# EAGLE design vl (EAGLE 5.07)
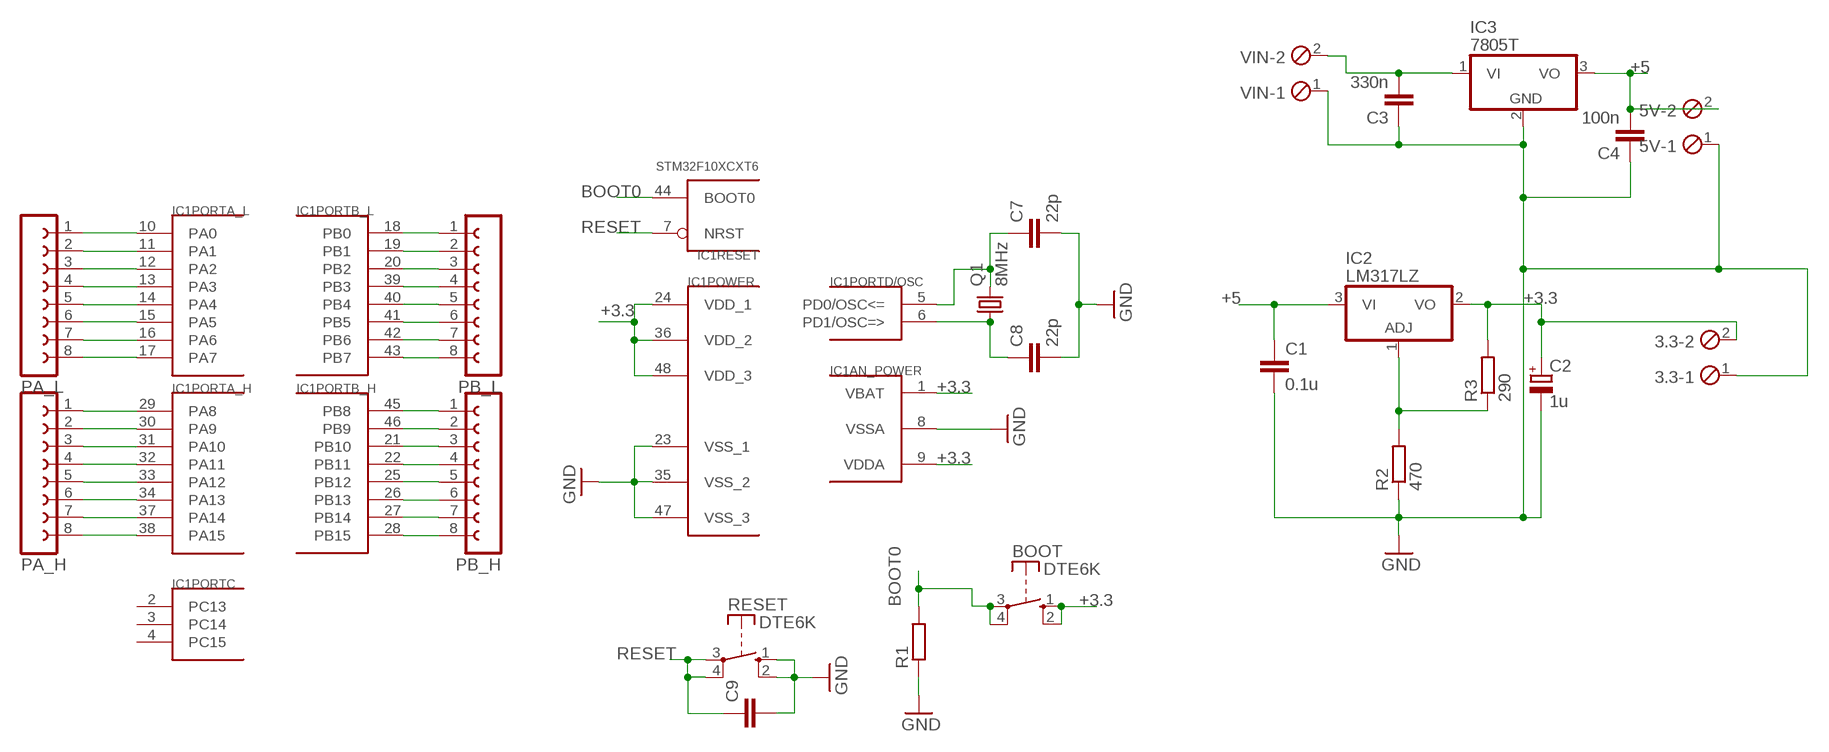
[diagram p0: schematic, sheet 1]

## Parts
3.3  MPT2  [2POL254]
5V  MPT2  [2POL254]
BOOT  DTE6K  [DTE6K]
C1  0.1u  C-EUC0805  [C0805]
C2  1u  CPOL-EUE2.5-6  [E2,5-6]
C3  330n  C-EUC0805  [C0805]
C4  100n  C-EUC0805  [C0805]
C7  22p  C-EUC0805  [C0805]
C8  22p  C-EUC0805  [C0805]
C9  C-EUC0805  [C0805]
IC1  STM32F10XCXT6  [TQFP48]
IC2  LM317LZ  [TO92]
IC3  7805T  [TO220H]
PA_H  FE08-1  [FE08]
PA_L  FE08-1  [FE08]
PB_H  FE08-1  [FE08]
PB_L  FE08-1  [FE08]
Q1  8MHz  CRYSTALHC49S  [HC49/S]
R1  R-EU_R0805  [R0805]
R2  470  R-EU_R0805  [R0805]
R3  290  R-EU_R0805  [R0805]
RESET  DTE6K  [DTE6K]
VIN  MPT2  [2POL254]

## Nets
+3.3: 3.3.2 BOOT.1(S) BOOT.2(S) C2.+ IC1.1(AN_POWER:VBAT) IC1.9(AN_POWER:VDDA) IC1.24(POWER:VDD_1) IC1.36(POWER:VDD_2) IC1.48(POWER:VDD_3) IC2.2(VO) R3.2
+5: 5V.2 C1.1 C4.2 IC2.3(VI) IC3.3(VO)
BOOT0: BOOT.3(P) BOOT.4(P) IC1.44(RESET:BOOT0) R1.2
GND: 3.3.1 5V.1 C1.2 C2.- C3.1 C4.1 C7.2 C8.2 C9.2 IC1.8(AN_POWER:VSSA) IC1.23(POWER:VSS_1) IC1.35(POWER:VSS_2) IC1.47(POWER:VSS_3) IC3.2(GND) R1.1 R2.1 RESET.1(S) RESET.2(S) VIN.1
N$1: C8.1 IC1.6(PORTD/OSC:PD1/OSC=>) Q1.1
N$2: C7.1 IC1.5(PORTD/OSC:PD0/OSC<=) Q1.2
N$3: IC1.10(PORTA_L:PA0) PA_L.1
N$4: IC1.11(PORTA_L:PA1) PA_L.2
N$5: IC2.1(ADJ) R2.2 R3.1
N$6: IC1.12(PORTA_L:PA2) PA_L.3
N$7: IC1.13(PORTA_L:PA3) PA_L.4
N$8: IC1.14(PORTA_L:PA4) PA_L.5
N$9: IC1.15(PORTA_L:PA5) PA_L.6
N$10: IC1.16(PORTA_L:PA6) PA_L.7
N$11: IC1.17(PORTA_L:PA7) PA_L.8
N$12: IC1.29(PORTA_H:PA8) PA_H.1
N$13: IC1.30(PORTA_H:PA9) PA_H.2
N$14: IC1.31(PORTA_H:PA10) PA_H.3
N$15: IC1.32(PORTA_H:PA11) PA_H.4
N$16: IC1.33(PORTA_H:PA12) PA_H.5
N$17: IC1.34(PORTA_H:PA13) PA_H.6
N$18: IC1.37(PORTA_H:PA14) PA_H.7
N$19: IC1.38(PORTA_H:PA15) PA_H.8
N$20: IC1.18(PORTB_L:PB0) PB_L.1
N$21: IC1.19(PORTB_L:PB1) PB_L.2
N$22: IC1.20(PORTB_L:PB2) PB_L.3
N$23: IC1.39(PORTB_L:PB3) PB_L.4
N$24: IC1.40(PORTB_L:PB4) PB_L.5
N$25: IC1.41(PORTB_L:PB5) PB_L.6
N$26: IC1.42(PORTB_L:PB6) PB_L.7
N$27: IC1.43(PORTB_L:PB7) PB_L.8
N$28: IC1.46(PORTB_H:PB9) PB_H.2
N$29: IC1.45(PORTB_H:PB8) PB_H.1
N$30: IC1.21(PORTB_H:PB10) PB_H.3
N$31: IC1.22(PORTB_H:PB11) PB_H.4
N$32: IC1.25(PORTB_H:PB12) PB_H.5
N$33: IC1.26(PORTB_H:PB13) PB_H.6
N$34: IC1.27(PORTB_H:PB14) PB_H.7
N$35: IC1.28(PORTB_H:PB15) PB_H.8
N$36: C3.2 IC3.1(VI) VIN.2
RESET: C9.1 IC1.7(RESET:NRST) RESET.3(P) RESET.4(P)
Unconnected: IC1.2(PORTC:PC13) IC1.3(PORTC:PC14) IC1.4(PORTC:PC15)

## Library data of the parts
3.3 5V VIN = con-phoenix-254:MPT2: PHOENIX CONNECTOR
BOOT RESET = switch-misc:DT: ITT SWITCH
C1 C3 C4 C7-C9 = resistor:C-EU: CAPACITOR, European symbol
C2 = resistor:CPOL-EU: POLARIZED CAPACITOR, European symbol
IC1 = stm32:STM32F10XCXT6: ST STM32F101/103 48pin LQFP
IC2 = linear:*317: Positive VOLTAGE REGULATOR
IC3 = linear:78*: Positive VOLTAGE REGULATOR Source: http://cache.national.com/ds/LM/LM78L05.pdf http://www.fairchildsemi.com/ds/LM/LM7805.pdf
PA_H PA_L PB_H PB_L = con-lsta:FE08-1: FEMALE HEADER
Q1 = crystal:CRYSTAL: CRYSTAL
R1-R3 = resistor:R-EU_: RESISTOR, European symbol

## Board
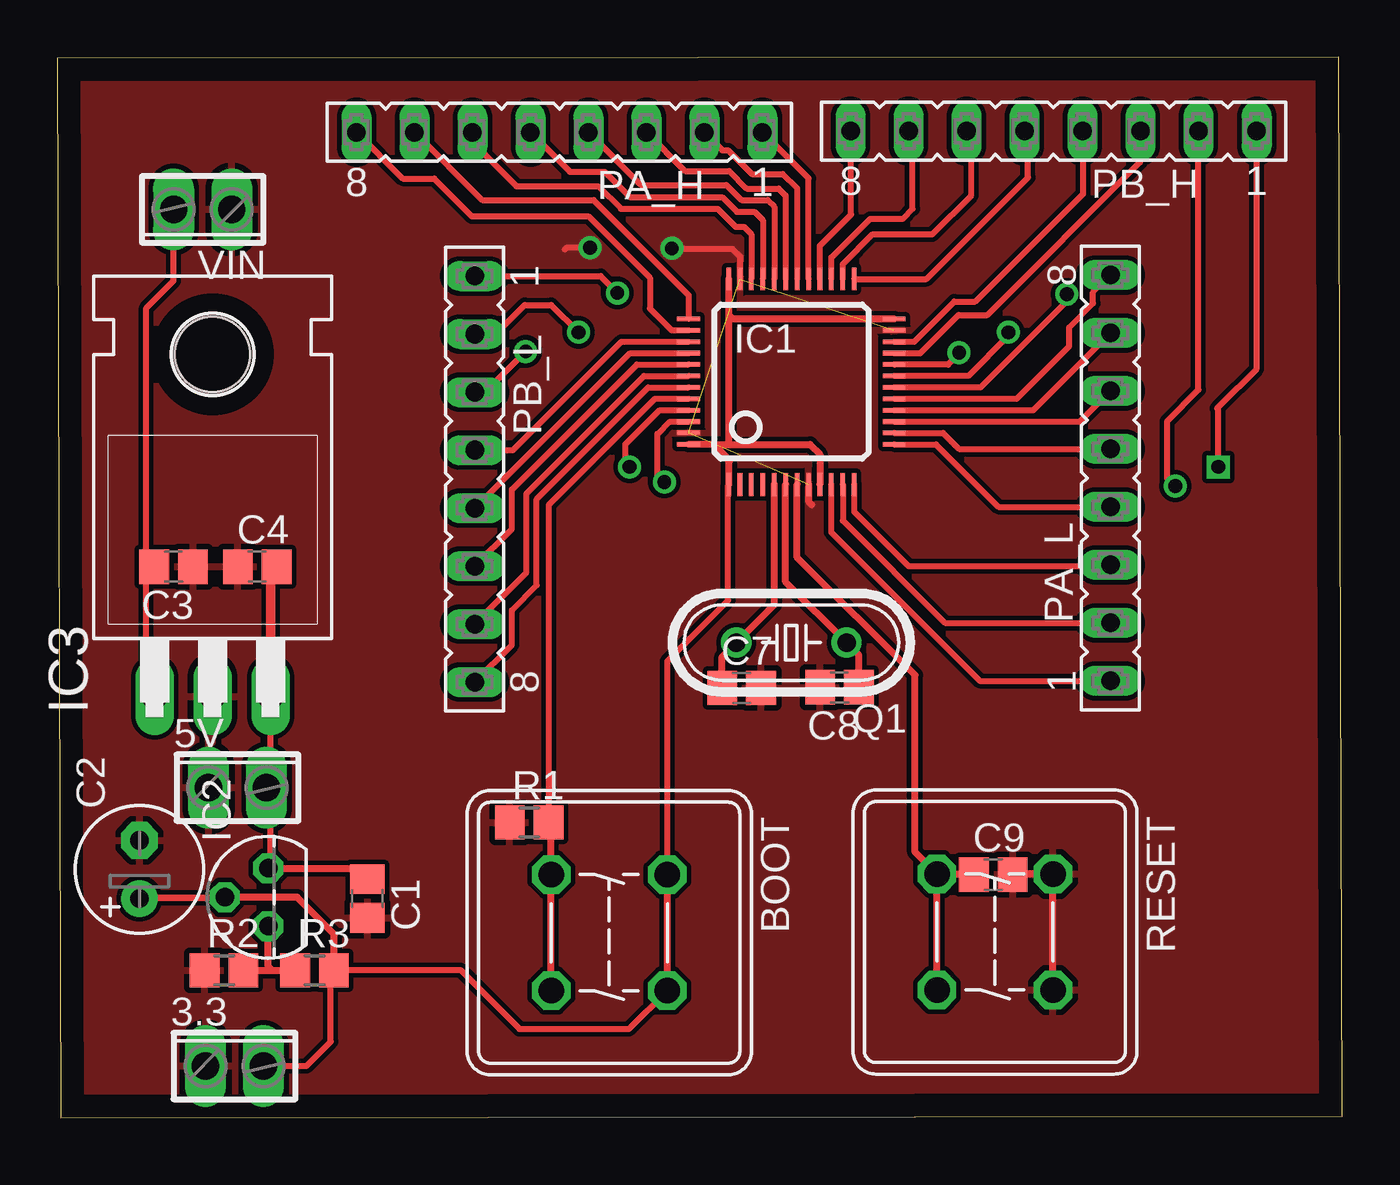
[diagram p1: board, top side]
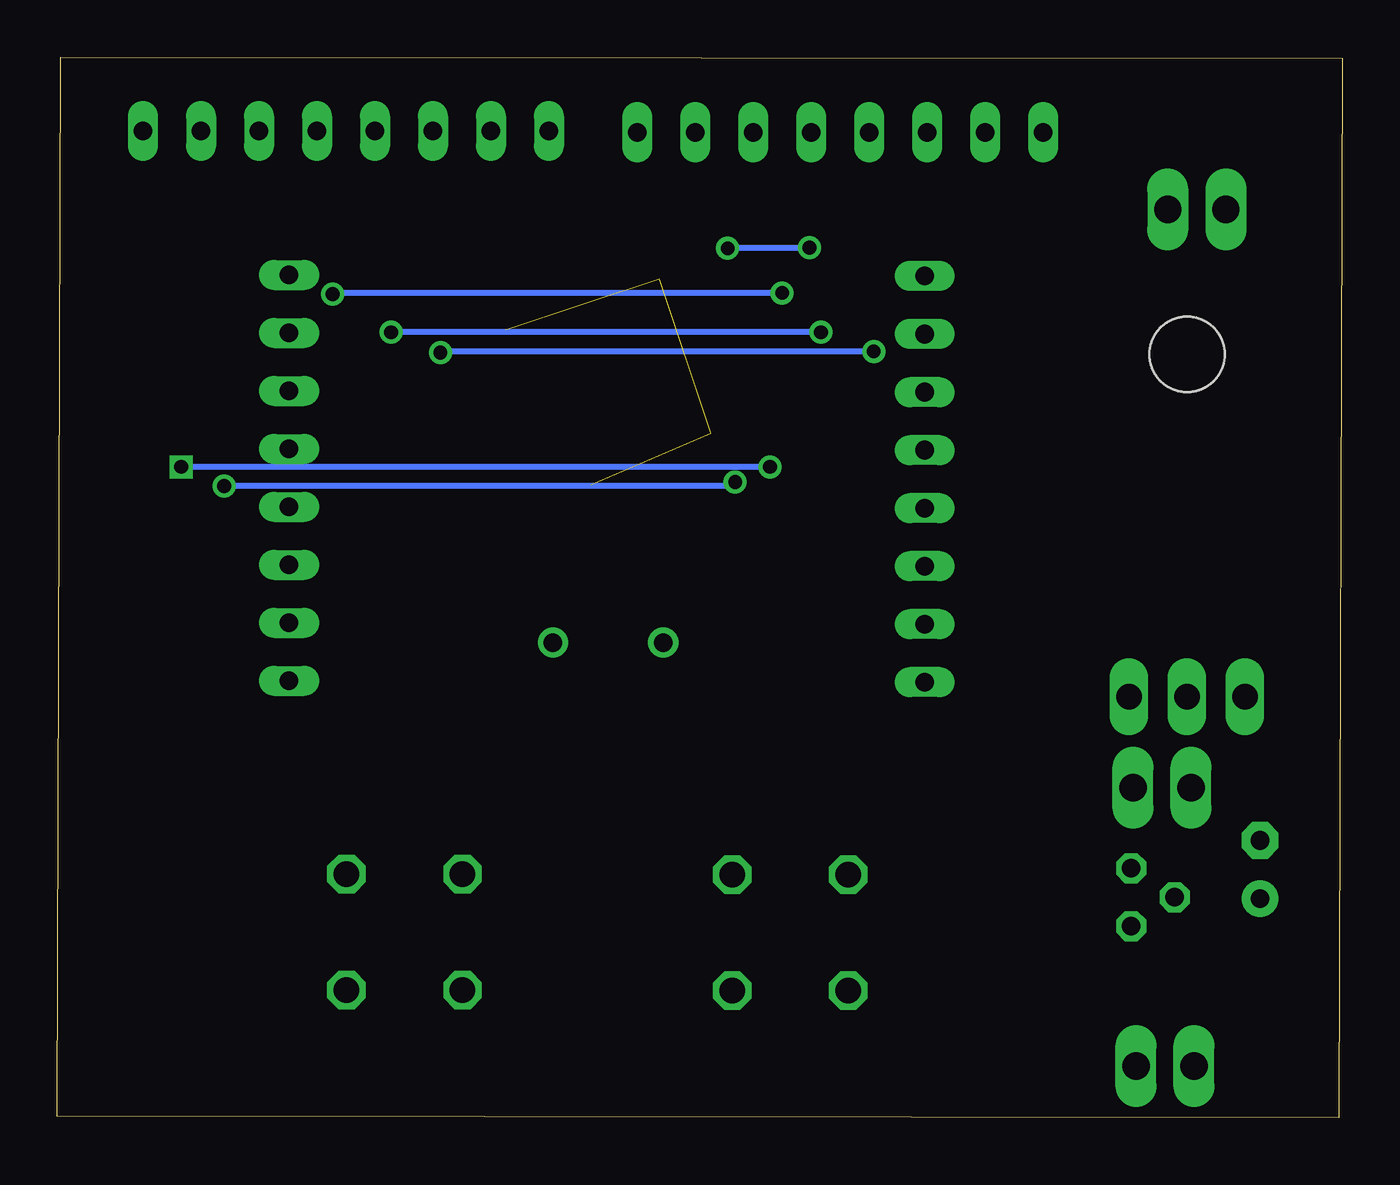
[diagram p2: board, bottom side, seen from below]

Size 56.29 x 46.45 mm. Coordinates in mm from the lower left corner, seen from the top.
Outline: 0.15,0 56.29,0.05 56.13,46.45 0,46.4 0.15,0
Copper layers (1*16): Top 0.035mm / dielectric 1.5mm / Bottom 0.035mm
Design rules "default": minimum track width 10mil, minimum drill 24mil, track to track 8mil, track to pad 8mil, pad to pad 8mil, via to via 8mil, smd to smd 8mil, copper to edge 40mil, drill to drill 8mil, minimum pad ring 10mil, minimum via ring 8mil, stop-mask expansion 4mil, vias tented up to drill 0mil, thermal gap 10mil

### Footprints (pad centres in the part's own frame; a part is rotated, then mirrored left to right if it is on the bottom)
2POL254 = drill 1.2 long: 1 -1.27,0; 2 1.27,0
DTE6K = drill 1.118 octagon: 1 -2.54,2.54; 2 2.54,2.54; 3 2.54,-2.54; 4 -2.54,-2.54
C0805 = smd 1.3 x 1.5: 1 -0.85,0; 2 0.85,0
E2,5-6 = drill 0.813 pad 1.6 round: + -1.27,0 | drill 0.813 pad 1.6 octagon: - 1.27,0
TQFP48 = smd 0.2 x 1: 1 -2.75,-4.5; 2 -2.25,-4.5; 3 -1.75,-4.5; 4 -1.25,-4.5; 5 -0.75,-4.5; 6 -0.25,-4.5; 7 0.25,-4.5; 8 0.75,-4.5; 9 1.25,-4.5; 10 1.75,-4.5; 11 2.25,-4.5; 12 2.75,-4.5; 25 2.75,4.5; 26 2.25,4.5; 27 1.75,4.5; 28 1.25,4.5; 29 0.75,4.5; 30 0.25,4.5; 31 -0.25,4.5; 32 -0.75,4.5; 33 -1.25,4.5; 34 -1.75,4.5; 35 -2.25,4.5; 36 -2.75,4.5 | smd 1 x 0.2: 13 4.5,-2.75; 14 4.5,-2.25; 15 4.5,-1.75; 16 4.5,-1.25; 17 4.5,-0.75; 18 4.5,-0.25; 19 4.5,0.25; 20 4.5,0.75; 21 4.5,1.25; 22 4.5,1.75; 23 4.5,2.25; 24 4.5,2.75; 37 -4.5,2.75; 38 -4.5,2.25; 39 -4.5,1.75; 40 -4.5,1.25; 41 -4.5,0.75; 42 -4.5,0.25; 43 -4.5,-0.25; 44 -4.5,-0.75; 45 -4.5,-1.25; 46 -4.5,-1.75; 47 -4.5,-2.25; 48 -4.5,-2.75
TO92 = drill 0.813 octagon: 1 -1.27,0; 2 0,1.905; 3 1.27,0
TO220H = drill 1.118 long: 1 -2.54,-10.16; 2 0,-10.16; 3 2.54,-10.16 | hole 3.302: 0,4.826
FE08 = drill 0.813 long: 1 -8.89,0; 2 -6.35,0; 3 -3.81,0; 4 -1.27,0; 5 1.27,0; 6 3.81,0; 7 6.35,0; 8 8.89,0
HC49/S = drill 0.813 round: 1 -2.413,0; 2 2.413,0
R0805 = smd 1.3 x 1.5: 1 -0.85,0; 2 0.85,0

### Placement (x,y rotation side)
3.3  7.77,2.26 0 top
5V  7.9,14.45 0 top
BOOT  24.18,8.1 270 top
C1  13.59,9.6 270 top
C2  3.61,10.87 90 top
C3  5.11,24.13 180 top
C4  8.76,24.13 0 top
C7  29.97,18.82 0 top
C8  34.26,18.85 180 top
C9  41,10.64 0 top
IC1  32.16,32.23 0 top
IC2  9.25,9.65 90 top
IC3  6.81,28.6 0 top
PA_H  22,43.15 180 top
PA_L  46.13,28.02 90 top
PB_H  43.64,43.21 180 top
PB_L  18.29,27.97 270 top
Q1  32.16,20.8 180 top
R1  20.68,12.93 0 top
R2  7.32,6.45 0 top
R3  11.28,6.45 0 top
RESET  41.07,8.13 270 top
VIN  6.38,39.78 180 top

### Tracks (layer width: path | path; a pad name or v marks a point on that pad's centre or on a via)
+3.3
  Top 0.254: 12.14,6.47 17.66,6.47 20.24,3.89 25.04,3.89 BOOT.2 | BOOT.1 26.72,19.99 29.39,22.66 29.39,27.71 IC1.1 | C2.+ 3.56,9.55 | 3.3.2 10.92,2.26 11.99,3.33 11.99,6.31 R3.2
  Top 0.305: 28.76,29.48 IC1.48 | 28.76,29.48 29.39,28.85 29.39,28.83 29.44,28.78 29.44,28.73 29.41,28.7 IC1.1 | 29.36,29.48 32.98,29.48 33.4,29.06 IC1.9 | 28.76,29.48 29.36,29.48 | 29.36,29.48 29.41,29.54 29.41,35.15 | 29.41,35.15 IC1.36 | 7.85,9.65 10.52,9.65 12.14,8.03 12.14,6.47 R3.2 | 7.85,9.65 IC2.2 | C2.+ 7.82,9.63 7.85,9.65 | IC1.24 29.58,34.98 29.41,35.15 | BOOT.2 BOOT.1
+5
  Top 0.254: 9.35,14.94 9.35,11.02 IC2.3 | 9.35,14.94 IC3.3 | 5V.2 9.17,14.76 9.35,14.94
  Top 0.305: IC2.3 13.12,10.92 C1.1
  Top 0.406: C4.2 9.35,24.13 IC3.3
BOOT0
  Top 0.254: IC1.44 26.17,31.48 21.54,26.85 21.54,13.03 21.95,12.62 21.83,12.62 R1.2
  Top 0.305: BOOT.3 BOOT.4 21.64,12.81 R1.2
GND  (via drill 0.6)  (3 unrouted)
  Top 0.254: IC1.35 29.91,37.71 29.57,38.05 26.95,38.05 v26.92,38.07 | v23.34,38.1 22.3,38.1 22.23,38.02
  Top 0.305: C9.2 41.87,10.67 RESET.1 RESET.2 | IC1.8 32.91,26.99 33.05,26.85
  Bottom 0.254: v26.92,38.07 23.37,38.07 v23.34,38.1
  pour Top: 0.15,50.8 55.98,50.72 55.98,0.43 0.15,0.61
N$1
  Top 0.305: IC1.6 31.91,23.47 Q1.1 35.11,20.26 C8.1
N$2
  Top 0.305: IC1.5 31.41,22.47 Q1.2 29.12,20.18 C7.1
N$3
  Top 0.254: IC1.10 33.91,25.63 40.41,19.13 PA_L.1
N$4
  Top 0.254: IC1.11 34.41,26.15 38.89,21.67 PA_L.2
N$5
  Top 0.305: 9.42,6.45 R3.1 | R2.2 9.42,6.45 | IC2.1 9.25,6.63 9.42,6.45
N$6
  Top 0.254: IC1.12 34.91,26.54 37.29,24.16 46.08,24.16 PA_L.3
N$7
  Top 0.254: IC1.13 38.49,29.48 41.22,26.75 PA_L.4
N$8
  Top 0.254: IC1.14 38.8,29.98 39.5,29.29 PA_L.5
N$9
  Top 0.254: IC1.15 44.78,30.48 PA_L.6
N$10
  Top 0.254: IC1.16 42.74,30.98 PA_L.7
N$11
  Top 0.254: IC1.17 42.02,31.48 44.32,33.78 44.32,34.62 45.36,35.66 45.36,36.14 PA_L.8
N$12
  Top 0.254: IC1.29 32.91,41.13 PA_H.1
N$13
  Top 0.254: IC1.30 32.41,40.69 31.78,41.33 30.43,41.33 29.39,42.37 29.13,42.37 PA_H.2
N$14
  Top 0.254: IC1.31 31.91,40.38 31.6,40.69 30.2,40.69 29.44,41.45 27.51,41.45 PA_H.3
N$15
  Top 0.254: IC1.32 31.41,39.89 31.12,40.18 29.97,40.18 29.31,40.84 25.58,40.84 PA_H.4
N$16
  Top 0.254: IC1.33 30.91,39.3 30.53,39.67 29.77,39.67 29.13,40.31 25.1,40.31 23.98,41.43 22.45,41.43 PA_H.5
N$17
  Top 0.254: IC1.34 30.41,38.68 30.07,39.01 29.72,39.01 28.93,39.8 24.69,39.8 23.7,40.79 20.12,40.79 18.26,42.65 18.26,43.08 PA_H.6
N$18
  Top 0.254: IC1.37 27.66,36.02 23.5,40.18 18.62,40.18 PA_H.7
N$19
  Top 0.254: IC1.38 26.91,34.48 25.96,35.43 25.96,36.78 23.27,39.47 18.16,39.47 16.51,41.12 15.14,41.12 PA_H.8
N$20  (via drill 0.6)
  Top 0.254: PB_L.1 23.8,36.86 v24.54,36.12 | v44.22,36.07 44.22,35.76 40.44,31.98 IC1.18
  Bottom 0.254: v24.54,36.12 44.17,36.12 v44.22,36.07
N$21  (via drill 0.6)
  Top 0.254: 22.76,34.32 v22.83,34.39 21.64,35.59 20.47,35.59 19.2,34.32 PB_L.2 | v41.66,34.39 41.66,34.24 39.9,32.49 IC1.19
  Bottom 0.254: v22.83,34.39 v41.66,34.39
N$22  (via drill 0.6)
  Top 0.254: PB_L.3 18.75,31.78 v20.52,33.55 | v39.5,33.5 39.5,33.45 39.01,32.97 36.67,32.97 IC1.20
  Bottom 0.254: v20.52,33.55 39.45,33.55 v39.5,33.5
N$23
  Top 0.254: PB_L.4 19.96,29.24 24.71,33.99 IC1.39
N$24
  Top 0.254: PB_L.5 18.31,26.7 25.1,33.48 IC1.40
N$25
  Top 0.254: IC1.41 25.39,32.98 19.91,27.51 19.91,25.78 PB_L.6
N$26
  Top 0.254: IC1.42 25.7,32.48 20.55,27.33 20.55,23.88 PB_L.7
N$27
  Top 0.254: IC1.43 25.89,31.98 21.01,27.1 21.01,23.32 19.91,22.22 19.91,20.7 PB_L.8
N$28  (via drill 0.6)
  Top 0.254: PB_H.2 49.99,31.88 48.62,30.51 48.62,28.02 | IC1.46 26.83,30.48 26.29,29.95 26.29,27.99 26.39,27.89 | 26.39,27.89 26.54,27.89 v26.59,27.84 26.44,27.84 26.39,27.89 | 48.62,28.02 48.62,27.99 48.77,27.84 | v48.97,27.66 48.62,28.02
  Bottom 0.254: v48.97,27.66 26.77,27.66 v26.59,27.84
N$29  (via drill 0.6)
  Top 0.254: PB_H.1 52.53,32.79 50.91,31.18 50.85,31.11 | 50.85,31.11 50.8,31.06 | IC1.45 26.39,30.98 24.89,29.49 24.89,28.68 v25.07,28.5 | v50.85,28.5 50.85,31.11
  Bottom 0.254: v25.07,28.5 v50.85,28.5
N$30
  Top 0.254: IC1.21 37.8,33.48 39.47,35.15 40.74,35.15 47.42,41.83 47.42,43.18 PB_H.3
N$31
  Top 0.254: IC1.22 37.54,33.98 39.29,35.74 40.21,35.74 44.93,40.46 44.93,43.18 PB_H.4
N$32
  Top 0.254: IC1.25 38.08,36.73 42.52,41.17 42.52,43.05 PB_H.5
N$33
  Top 0.254: IC1.26 34.41,37.38 35.71,38.68 38.33,38.68 40.03,40.39 40.03,43 PB_H.6
N$34
  Top 0.254: IC1.27 33.91,37.67 35.61,39.37 37.03,39.37 37.47,39.8 37.47,43.03 PB_H.7
N$35
  Top 0.254: IC1.28 33.41,38.18 34.77,39.55 34.77,43.18 PB_H.8
N$36
  Top 0.254: VIN.2 5.11,36.65 3.91,35.46 3.91,24.16 3.91,18.8 IC3.1
  Top 0.406: C3.2 3.91,24.13 3.91,24.16
RESET
  Top 0.305: RESET.4 40.12,10.67 C9.1 | RESET.3 RESET.4 | IC1.7 32.41,24.54 37.57,19.38 37.57,11.63 RESET.4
